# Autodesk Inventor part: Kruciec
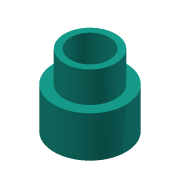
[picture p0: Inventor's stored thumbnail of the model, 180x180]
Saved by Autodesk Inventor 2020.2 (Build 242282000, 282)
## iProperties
Created: 2006-01
Part Number: Kruciec
Document SubType Name: Modeling
Designer: F.Stasiak
Density: 1 g/cm^3
Material: Ogólny
Appearance: Turkus
Manager: www.cadconsulting.pl
Company: Fabian Stasiak CAD Consulting
Author: F.Stasiak
Subject: Zbiór ćwiczeń. Autodesk Inventor 2020. Kurs podstawowy
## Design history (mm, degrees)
sketch "Szkic1"
  geometry: C1 r 17.5 at (1.592, 0); 1 further point
  constraints: 1 centre point
  dimensions: "d0" = 35 diameter of C1
extrude "Wyciągnięcie proste1" new body sketch "Szkic1" distance "d1" = 20; taper "d2" = 0 deg
sketch "Szkic2"
  geometry: C1 r 17.5 at (0, 0) reference; C2 r 12.5 at (0, 0)
  constraints: 1 centre point, 1 coincident
  dimensions: "d3" = 25 diameter of C2
extrude "Wyciągnięcie proste2" join sketch "Szkic2" distance "d4" = 15; taper "d5" = 0 deg
feature "Skorupa1" dims "d6" = 3
feature "Gwint1" dims "d7" = 15, "d8" = 0
node "Bryła1"
node "Korpusy bryłowe"
node "Korpusy powierzchniowe"
